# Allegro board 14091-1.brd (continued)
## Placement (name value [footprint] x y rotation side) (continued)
PR4535  140KR2F-1-GP  [R402H16]  154.08 23.62 0 bottom
PR4599  100KR2J-1-GP  [R402H16]  148.37 20.57 180 bottom
PR4601  2D2R3-1-U-GP  [R603H22]  32.42 207.65 90 bottom
PR4602  4K7R2F-GP  [R402H16]  20.86 209.17 180 bottom
PR4603  1KR2F-3-GP  [R402H16]  22.64 195.2 180 top
PR4605  1KR2F-3-GP  [R402H16]  23.15 204.49 270 top
PR4606  2K61R2F-1-GP  [R402H16]  20.61 195.2 0 top
PR4608  13K7R2F-GP  [R402H16]  19.72 198.63 270 bottom
PR4609  0R2J-2-GP  [R402H16]  25.69 190.5 0 top
PR4610  NTC-100K-12-GP-U  [NTC-402H22-U]  40.42 168.53 90 top
PR4612  20KR2F-L-GP  [R402H16]  19.34 203.58 270 bottom
PR4613  32K4R2F-1-GP  [R402H16]  23.15 202.61 270 top
PR4614  84K5R2F-GP  [R402H16]  23.15 200.7 90 top
PR4615  10KR2F-2-GP  [R402H16]  19.59 192.41 0 bottom
PR4616  100R2F-L1-GP-U  [R402H14]  23.66 192.41 180 top
PR4617  2K43R2F-GP  [R402H16]  23.02 208.03 0 top
PR4618  45D3R2F-L-GP  [R402H16]  24.67 190.5 0 top
PR4620  51KR2F-L-GP  [R402H16]  23.15 198.81 270 top
PR4621  140KR2F-1-GP  [R402H16]  25.69 194.31 180 bottom
PR4622  100KR2F-L1-GP  [R402H16]  19.34 206.76 90 bottom
PR4623  7K5R3F-2-GP  [R603H22]  26.96 192.79 0 top
PR4624  1KR2F-3-GP  [R402H16]  19.59 209.63 0 bottom
PR4625  13K7R2F-GP  [R402H16]  29.88 192.41 0 top
PR4626  30K9R2F-GP  [R402H16]  19.34 205.61 270 bottom
PR4627  7K5R3F-2-GP  [R603H22]  19.34 197.21 90 bottom
PR4628  49D9R2F-GP  [R402H16]  19.34 207.77 90 bottom
PR4629  59KR2F-GP  [R402H16]  28.61 195.2 180 bottom
PR4630  14K7R2F-L-GP  [R402H16]  23.3 208.15 270 bottom
PR4631  1K24R2F-GP  [R402H16]  29.47 191.97 90 bottom
PR4632  NTC-100K-12-GP-U  [NTC-402H22-U]  42.45 186.31 90 top
PR4633  220KR2F-GP  [R402H16]  22.84 211.46 0 bottom
PR4635  1K24R2F-GP  [R402H16]  30.36 196.06 0 top
PR4636  110KR3F-GP  [R603H22]  30.39 210.57 180 bottom
PR4637  523KR2F-GP  [R402H16]  23.86 211.46 180 bottom
PR4638  1KR2F-3-GP  [R402H16]  29.12 208.66 90 top
PR4639  2D2R3-1-U-GP  [R603H22]  32.29 209.55 0 top
PR4640  909R2F-GP  [R402H16]  32.55 195.2 180 bottom
PR4641  4K99R2F-L-GP  [R402H16]  32.39 196.06 180 top
PR4642  110KR3F-GP  [R603H22]  25.76 211.71 270 bottom
PR4644  NTC-100K-12-GP-U  [NTC-402H22-U]  34.2 186.31 90 top
PR4645  12K7R2F-GP  [R402H16]  32.42 192.91 90 bottom
PR4646  2D2R3-1-U-GP  [R603H22]  32.29 196.85 270 bottom
PR4647  909R2F-GP  [R402H16]  31.53 210.19 0 bottom
PR4648  12K7R2F-GP  [R402H16]  33.05 209.8 90 bottom
PR4649  NTC-100K-12-GP-U  [NTC-402H22-U]  52.74 217.3 270 top
PR4650  22K6R2F-1-GP  [R402H16]  29.62 203.45 270 top
PR4651  NTC-220K-GP-U  [NTC-402H22-U]  55.28 217.3 270 top
PR4652  1KR2F-3-GP  [R402H16]  26.45 207.77 270 bottom
PR4653  3K57R2F-GP  [R402H16]  29.12 210.19 0 bottom
PR4654  14KR2F-GP  [R402H16]  29.62 204.47 270 top
PR4655  12K4R2F-GP  [R402H16]  28.48 200.28 270 top
PR4656  10R2F-L-GP  [R402H14]  28.1 210.19 180 bottom
PR4657  10R2F-L-GP  [R402H14]  26.96 210.19 180 bottom
PR4658  3K57R2F-GP  [R402H16]  25.94 210.19 0 bottom
PR4660  0R0402-PAD-2-GP  [0R0402-PAD-1]  22.64 195.2 0 bottom
PR4661  2KR2F-3-GP  [R402H16]  33.41 196.06 0 top
PR4662  49D9R2F-GP  [R402H16]  21.62 195.2 0 bottom
PR4663  100R2F-L1-GP-U  [R402H14]  24.67 195.2 0 bottom
PR4664  1KR2F-3-GP  [R402H16]  24.67 192.41 180 top
PR4665  -  [0R0402-PAD]  19.59 195.2 180 bottom
PR4666  -  [0R0402-PAD]  20.61 195.2 180 bottom
PR4667  2D2R3F-L-GP  [R603H24]  32.77 200.18 270 bottom
PR4668  10R2F-L-GP  [R402H14]  23.66 195.2 0 bottom
PR4669  2KR2F-3-GP  [R402H16]  19.59 195.2 180 top
PR4701  -  [0R0805-PAD]  24.93 172.59 0 top
PR4702  -  [0R0805-PAD]  22.89 172.59 0 top
PR4703  -  [0R0805-PAD]  20.86 172.59 0 top
PR4704  -  [0R0805-PAD]  20.86 172.59 180 bottom
PR4705  -  [0R0805-PAD]  22.89 172.59 180 bottom
PR4706  -  [0R0805-PAD]  24.93 172.59 180 bottom
PR4707  2D2R5J-1-GP  [R805H24]  29.12 186.94 270 top
PR4801  -  [0R0805-PAD]  32.55 216.79 0 bottom
PR4802  -  [0R0805-PAD]  35.47 215.82 270 bottom
PR4803  -  [0R0805-PAD]  28.48 216.79 0 bottom
PR4805  -  [0R0805-PAD]  43.21 192.15 0 bottom
PR4806  -  [0R0805-PAD]  35.09 192.15 0 bottom
PR4807  -  [0R0805-PAD]  37.12 192.15 0 bottom
PR4808  -  [0R0805-PAD]  39.15 192.15 0 bottom
PR4809  -  [0R0805-PAD]  35.47 213.87 270 bottom
PR4810  -  [0R0805-PAD]  30.51 216.79 0 bottom
PR4811  -  [0R0805-PAD]  45.25 192.15 0 bottom
PR4812  -  [0R0805-PAD]  41.18 192.15 0 bottom
PR4813  2D2R5J-1-GP  [R805H24]  45.63 212.98 90 bottom
PR4814  2D2R5J-1-GP  [R805H24]  46.13 197.74 90 bottom
PR5001  -  [0R0805-PAD]  27.72 166.75 90 top
PR5002  -  [0R0805-PAD]  27.72 168.78 90 top
PR5004  -  [0R0805-PAD]  27.72 170.81 90 top
PR5005  2D2R2F-GP  [R402H16]  23.43 164.97 270 top
PR5101  620KR2F-GP  [R402H16]  79.92 215.14 270 bottom
PR5102  39K2R2F-L-GP  [R402H16]  80.17 208.91 0 bottom
PR5103  2D2R3-1-U-GP  [R603H22]  90.58 210.82 270 bottom
PR5105  5D1R2F-GP  [R402H16]  82.96 216.92 270 bottom
PR5106  10KR2F-2-GP  [R402H16]  81.44 216.41 180 bottom
PR5108  -  [0R0805-PAD]  90.33 208.28 270 top
PR5110  48D7KR2F-GP  [R402H16]  81.19 208.91 180 bottom
PR5111  7K5R2F-1DL-GP  [R402H16]  86.9 216.79 180 bottom
PR5112  -  [0R0805-PAD]  82.08 223.77 270 bottom
PR5114  2D2R5J-1-GP  [R805H24]  97.44 221.23 0 bottom
PR5116  -  [0R0805-PAD]  90.33 206.25 270 top
PR5118  -  [0R0603-PAD]  85.63 216.79 0 bottom
PR5121  -  [0R0805-PAD]  82.08 219.71 270 bottom
PR5122  -  [0R0805-PAD]  80.68 205.99 0 bottom
PR5125  -  [0R0805-PAD]  82.71 205.99 0 bottom
PR5127  -  [0R0805-PAD]  82.08 221.74 270 bottom
PR5202  470KR2F-GP  [R402H16]  22.26 151.89 90 top
PR5204  -  [0R0805-PAD]  30.26 141.48 180 top
PR5207  23K7R2F-GP  [R402H16]  22.26 152.91 90 top
PR5208  10KR2F-2-GP  [R402H16]  22.26 153.92 270 top
PR5210  2D2R3-1-U-GP  [R603H22]  24.77 149 180 top
PR5212  10KR2J-3-GP  [R402H16]  22.26 147.57 90 top
PR5214  2D2R5J-1-GP  [R805H24]  35.72 149.73 90 bottom
PR5215  -  [0R0805-PAD]  26.2 141.48 180 top
PR5217  0R2J-2-GP  [R402H16]  21.88 150.37 0 top
PR5218  10KR2J-3-GP  [R402H16]  22.26 148.84 270 top
PR5219  40K2R2F-GP  [R402H16]  22.74 145.11 270 bottom
PR5221  -  [0R0805-PAD]  28.23 141.48 180 top
PR5242  10KR2F-2-GP  [R402H16]  95.16 122.3 0 top
PR5245  -  [0R0402-PAD]  89.57 119.89 0 top
PR5246  10KR2J-3-GP  [R402H16]  84.41 124.21 180 top
PR5257  1KR2J-1-GP  [R402H16]  91.09 120.27 270 top
PR5258  -  [0R0805-PAD]  32.29 141.48 180 top
PR5297  100KR2J-1-GP  [R402H16]  35.47 48.77 90 bottom
PR5298  120KR2F-L-GP  [R402H16]  35.47 47.75 270 bottom
PR5301  10R3J-3-GP  [R603H22]  116.37 70.61 0 top
PR5302  10KR2F-2-GP  [R402H16]  118.52 70.36 0 top
PR5303  2D2R6J-3-GP  [R1206H28]  112.15 68.88 270 top
PR5304  10KR2F-2-GP  [R402H16]  120.94 78.99 0 top
PR5305  20KR2F-L-GP  [R402H16]  119.54 70.36 180 top
PR5306  0R0402-PAD-2-GP  [0R0402-PAD-1]  122.97 79.12 0 top
PR5307  -  [0R0805-PAD]  125.89 72.26 90 top
PR5308  -  [0R0805-PAD]  125.89 74.3 90 top
PR5309  -  [0R0805-PAD]  101.38 78.49 270 top
PR5310  -  [0R0805-PAD]  101.38 74.42 270 top
PR5311  -  [0R0805-PAD]  101.38 76.45 270 top
PR5312  0R2J-2-GP  [R402H16]  117.51 78.49 180 top
PR5313  0R2J-2-GP  [R402H16]  118.7 79.43 0 top
PR5431  10KR2J-3-GP  [R402H16]  141.64 8.13 270 bottom
PR5478  1KR2J-1-GP  [R402H16]  135.92 101.73 90 top
PR5479  1KR2J-1-GP  [R402H16]  135.92 96.65 90 top
PR5480  1KR2J-1-GP  [R402H16]  135.92 98.68 90 bottom
PR5481  1R2F-GP  [R402H16]  122.97 98.04 180 top
PR5482  1KR2J-1-GP  [R402H16]  135.92 95.63 90 bottom
PR5485  1KR2J-1-GP  [R402H16]  135.92 101.73 90 bottom
PR5486  1KR2J-1-GP  [R402H16]  135.92 99.69 90 bottom
PR5487  0R0603-PAD-2-GP-U  [0R0603-PAD-1-U]  120.68 96.9 180 top
PR5488  9K31R2F-GP  [R402H16]  124.37 94.36 180 top
PR5489  1R2F-GP  [R402H16]  118.14 100.97 270 top
PR5490  1KR2J-1-GP  [R402H16]  135.92 97.66 90 top
PR5491  11KR2F-L-GP  [R402H16]  119.67 100.33 180 top
PR5492  2D2R5J-1-GP  [R805H24]  126.91 84.58 90 top
PR5498  2D2R5J-1-GP  [R805H24]  137.96 16 0 bottom
PR8401  56KR2F-GP  [R402H16]  115.6 100.84 0 top
PR8402  2D2R2F-GP  [R402H16]  114.97 104.39 270 top
PR8403  33KR2F-GP  [R402H16]  114.59 100.84 180 top
PR8404  100KR2J-1-GP  [R402H16]  108.62 100.97 180 top
PR8405  18KR2F-GP  [R402H16]  112.56 100.84 0 top
PR8501  10KR2J-3-GP  [R402H16]  107.86 68.83 0 top
PR8502  10R2F-L-GP  [R402H14]  84.87 76.33 0 top
PR8503  10KR2F-2-GP  [R402H16]  88.04 76.33 180 top
PR8504  6K98R2F-GP  [R402H16]  86.9 76.33 0 top
PR8505  -  [0R0402-PAD]  103.79 68.83 0 top
PR8506  -  [0R0805-PAD]  90.84 206.25 90 bottom
PR8507  -  [0R0805-PAD]  90.84 208.28 90 bottom
PR8509  0R2J-2-GP  [R402H16]  25.18 146.3 90 top
PR8510  0R0402-PAD-2-GP  [0R0402-PAD-1]  22.26 146.56 270 top
PR8511  0R0402-PAD-2-GP  [0R0402-PAD-1]  22.26 145.54 270 top
PR8512  0R2J-2-GP  [R402H16]  13.5 186.06 180 top
PR8513  0R2J-2-GP  [R402H16]  107.6 100.97 0 top
PR8514  10KR2F-2-GP  [R402H16]  110.14 99.82 90 top
PR8515  0R2J-2-GP  [R402H16]  121.95 79.6 180 top
PR8516  10KR2F-2-GP  [R402H16]  121.95 69.9 270 top
PR8517  0R2J-2-GP  [R402H16]  133.38 105.03 270 bottom
PR8518  0R2J-2-GP  [R402H16]  106.84 68.83 0 top
PR8519  3K3R2J-3-GP  [R402H16]  82.58 59.05 180 top
PR8520  3K3R2J-3-GP  [R402H16]  83.6 59.05 180 top
PR8521  0R2J-2-GP  [R402H16]  103.03 66.93 0 bottom
PR8522  100KR2F-L1-GP  [R402H16]  24.67 69.09 180 bottom
PR8523  100KR2J-1-GP  [R402H16]  36.36 56.77 0 top
PR8524  1MR2J-1-GP  [R402H16]  35.85 54.1 270 top
PR8527  0R2J-2-GP  [R402H16]  164.5 175.64 180 top
PSWD1  JOWLE-CON2-5-GP  [A2541WV0-1EX2PA-6T]  123.6 112.01 90 top
PT1  E820U2D5VM-14-GP  [ECAP-100D6D3H355]  106.08 95.63 0 top
PT2  SE47U25VM-14-GP  [SE361416H237]  137.32 76.2 90 top
PT3  E820U2D5VM-14-GP  [ECAP-100D6D3H355]  113.95 95.63 0 top
PT4  E820U2D5VM-14-GP  [ECAP-100D6D3H355]  106.08 87.5 0 top
PT4501  SE220U6D3VM-3GP  [SE3116H241]  135.03 7.87 90 top
PT4502  SE220U6D3VM-3GP  [SE3116H241]  145.07 7.87 90 top
PT4503  SE47U25VM-13-GP  [SE361414H241]  141.77 24.64 270 top
PT4504  SE47U25VM-13-GP  [SE361414H241]  132.37 24.64 90 top
PT4701  E820U2D5VM-6-GP  [ECAP-100D6D3H375]  52.74 186.56 0 top
PT4703  E820U2D5VM-6-GP  [ECAP-100D6D3H375]  52.87 178.69 90 top
PT4704  SE47U25VM-13-GP  [SE361414H241]  23.15 179.07 180 top
PT4801  E820U2D5VM-6-GP  [ECAP-100D6D3H375]  59.85 190.25 90 top
PT4802  E560U6D3VM-3-GP  [ECAP-100D6D3H375]  67.34 197.1 0 top
PT4803  SE47U25VM-13-GP  [SE361414H241]  37.88 208.41 0 top
PT4804  SE47U25VM-13-GP  [SE361414H241]  37.88 198.5 180 top
PT5001  E820U2D5VM-6-GP  [ECAP-100D6D3H375]  49.94 165.99 0 top
PT5101  SE330U2VDM-L-GP  [CT7343H83]  100.24 202.56 0 top
PT5102  SE330U2VDM-L-GP  [CT7343H83]  95.03 202.56 0 top
PT5103  SE47U25VM-13-GP  [SE361414H241]  88.3 216.28 0 top
PT5201  SE47U25VM-13-GP  [SE361414H241]  33.31 147.96 180 top
PT5202  E820U2D5VM-6-GP  [ECAP-100D6D3H375]  54.64 146.43 0 top
PT5203  E820U2D5VM-6-GP  [ECAP-100D6D3H375]  55.66 154.31 0 top
PT8501  E820U2D5VM-6-GP  [ECAP-100D6D3H375]  81.44 70.87 90 top
PU1  SIRA14DP-T1-GE3-GP  [PPAK-5PH45]  129.57 80.26 270 top
PU2  SIRA14DP-T1-GE3-GP  [PPAK-5PH45]  129.57 80.26 90 bottom
PU3  SIRA04DP-T1-GE3-GP  [PPAK-5PH45]  127.54 88.9 90 top
PU4401  SIS412DN-T1-GE3-GP  [PPAK-8P-2H45]  43.21 54.99 0 bottom
PU4402  SIS412DN-T1-GE3-GP  [PPAK-8P-2H45]  38.77 56.52 180 bottom
PU4403  AO4407AL-GP  [SOIC8H69]  64.93 37.47 180 top
PU4404  BQ24727RGRR-1-GP  [QFN20G3D5-G2D15H40]  42.32 45.21 90 bottom
PU4405  AO4407AL-GP  [SOIC8H69]  40.8 71.37 180 top
PU4501  RT8243BZQW-GP  [QFN20-G1D75H32]  152.69 22.23 270 top
PU4502  AON7506-GP  [PPAK-8P-3232H36]  141.13 19.3 0 bottom
PU4503  AON7410-GP  [PPAK-8P-3232H36]  145.58 20.83 180 bottom
PU4504  AON7506-GP  [PPAK-8P-3232H36]  134.78 19.3 0 bottom
PU4505  AON7410-GP  [PPAK-8P-3232H36]  130.34 20.83 180 bottom
PU4601  NCP81206MNTXG-GP-U3  [LFQFN52J6-G4D8-1H40]  25.94 201.55 180 bottom
PU4701  AON6520-GP  [PPAK-8P-5262H40]  30.39 175.9 90 top
PU4702  AON6510-GP  [PPAK-8P-5262H40]  32.16 182.5 270 top
PU4703  AON6510-GP  [PPAK-8P-5262H40]  32.16 182.5 90 bottom
PU4704  AON6520-GP  [PPAK-8P-5262H40]  30.39 175.9 270 bottom
PU4801  AON6520-GP  [PPAK-8P-5262H40]  44.99 215.26 90 top
PU4802  AON6510-GP  [PPAK-8P-5262H40]  46.77 208.66 90 bottom
PU4803  AON6510-GP  [PPAK-8P-5262H40]  46.77 208.66 270 top
PU4804  AON6520-GP  [PPAK-8P-5262H40]  44.99 195.45 90 top
PU4805  AON6510-GP  [PPAK-8P-5262H40]  46.77 202.06 90 bottom
PU4807  AON6510-GP  [PPAK-8P-5262H40]  46.77 202.06 270 top
PU5001  AON7410-GP  [PPAK-8P-3232H36]  33.43 166.12 90 top
PU5002  AON7506-GP  [PPAK-8P-3232H36]  34.96 161.67 270 top
PU5003  NCP81253MNTBG-GP-U2  [LFDFN8G2-G1309H40]  26.7 162.18 90 top
PU5102  AON6510-GP  [PPAK-8P-5262H40]  101.76 220.6 0 bottom
PU5103  AON6520-GP  [PPAK-8P-5262H40]  93 222.5 180 bottom
PU5104  RT8207PGQW-GP  [QFN20-G1D75H32]  85.25 211.58 0 bottom
PU5201  RT8237CZQW-2-GP  [DFN10G3-G265175H32]  23.66 149.1 270 bottom
PU5202  AON6520-GP  [PPAK-8P-5262H40]  34.7 145.41 270 bottom
PU5203  AON6510-GP  [PPAK-8P-5262H40]  36.48 154.05 90 bottom
PU5301  RT6220AGQUF-GP  [QFN16J3H24]  119.54 74.93 270 top
PU5302  APL5930KAI-TRG-1-GP  [SOIC8-G3530H63]  89.7 124.33 90 top
PU5409  SIRA04DP-T1-GE3-GP  [PPAK-5PH45]  127.54 88.9 270 bottom
PU8401  RT8068AZQWID-GP-U  [DFN10G3-G265175H32]  111.41 104.39 90 top
PU8501  APL5912-KAC-TRG-GP  [SOIC8-G3530H63]  95.66 68.45 270 top
PWRCN1  ACES-CON10-30-GP  [51530-01041-W01]  26.75 22.5 270 top
Q1  2N7002A-7-GP  [SOT23DGS2D4H48]  41.94 116.2 270 top
Q2  MMBT3904-4-GP  [SOT23CBE2D4H44]  143.04 116.08 0 top
Q3  2N7002A-7-GP  [SOT23DGS2D4H48]  153.83 209.17 270 bottom
Q4  DMN5L06K-7-GP  [SOT23DGS2D4H48]  153.45 118.62 0 top
Q5  2N7002A-7-GP  [SOT23DGS2D4H48]  38.13 118.11 270 top
Q6  2N7002EDW-2-GP  [SOT-363H44]  150.53 77.98 0 top
Q8  2N7002H-GP  [SOT23DGS2D4H44]  126.53 44.58 180 top
Q10  MMBT3904-4-GP  [SOT23CBE2D4H44]  38.13 121.67 90 top
Q12  2N7002A-7-GP  [SOT23DGS2D4H48]  163.99 46.23 90 bottom
Q22  MMBT3904-4-GP  [SOT23CBE2D4H44]  42.71 28.32 270 bottom
Q24  AZ5125-02S-R7G-GP  [SOT23-2D4-312H46]  177.96 85.47 0 top
Q28  2N7002-11-GP  [SOT23DGS2D4H44]  168.56 87.25 270 top
Q31  MMBT3904-4-GP  [SOT23CBE2D4H44]  151.67 82.68 0 top
Q36  MMBT3904DW-GP  [SOT-363H44]  32.55 7.87 90 top
Q43  AO4468L-GP  [SOIC8H69]  124.62 7.75 90 bottom
Q44  AO3413L-GP  [SOT23DGS2D8H50]  41.94 6.86 180 bottom
Q45  MMBT3904-4-GP  [SOT23CBE2D4H44]  50.45 36.45 180 bottom
Q46  AZ5125-02S-R7G-GP  [SOT23-2D4-312H46]  84.11 41.66 270 top
Q47  2N7002A-7-GP  [SOT23DGS2D4H48]  55.02 36.32 0 bottom
Q48  MMBT3904-4-GP  [SOT23CBE2D4H44]  91.35 85.47 180 bottom
Q56  2N7002A-7-GP  [SOT23DGS2D4H48]  157.01 78.11 270 bottom
Q57  AZ5125-02S-R7G-GP  [SOT23-2D4-312H46]  174.02 85.47 0 top
Q65  2N7002KDW-1-GP  [SOT-363H44]  127.41 15.62 0 bottom
Q68  2N7002A-7-GP  [SOT23DGS2D4H48]  35.21 21.97 90 top
Q76  2N7002A-7-GP  [SOT23DGS2D4H48]  165.51 91.82 0 top
Q77  AO3413L-GP  [SOT23DGS2D8H50]  159.93 92.2 0 top
Q100  MMBT3904-4-GP  [SOT23CBE2D4H44]  42.96 6.99 0 top
Q101  MMBT3904-4-GP  [SOT23CBE2D4H44]  47.53 6.99 0 top
Q102  MMBT3904-4-GP  [SOT23CBE2D4H44]  46.52 6.99 0 bottom
Q123  2N7002KDW-1-GP  [SOT-363H44]  98.33 85.34 270 top
Q128  MMBT3904-4-GP  [SOT23CBE2D4H44]  150.02 209.17 90 bottom
Q1211  AO3413L-GP  [SOT23DGS2D8H50]  146.46 201.68 0 bottom
Q1212  2N7002A-7-GP  [SOT23DGS2D4H48]  25.18 12.83 180 bottom
Q1214  MMBT3904-4-GP  [SOT23CBE2D4H44]  25.94 27.18 0 bottom
Q1217  2N7002KDW-1-GP  [SOT-363H44]  122.08 16.26 90 bottom
Q1229  2N7002K-2-GP  [SOT23DGS2D4H44]  146.21 223.9 90 top
Q1249  2N7002A-7-GP  [SOT23DGS2D4H48]  143.8 30.23 270 top
Q1250  AO4286-GP  [SOIC8H69]  39.28 35.31 270 bottom
Q5008  2N7002A-7-GP  [SOT23DGS2D4H48]  151.93 55.24 90 top
Q6701  2N7002KDW-GP  [SOT-363H44]  102.78 64.9 270 top
Q6705  2N7002A-7-GP  [SOT23DGS2D4H48]  47.02 120.65 90 top
Q9501  2N7002KDW-GP  [SOT-363H44]  83.22 54.36 270 bottom
Q9502  2N7002KDW-GP  [SOT-363H44]  83.22 54.38 270 top
Q9503  2N7002KDW-GP  [SOT-363H44]  83.2 50.46 270 top
Q9601  AO3418L-GP  [SOT23DGS2D8H50]  62.01 66.17 180 bottom
Q9602  LMBT3906LT1G-1-GP  [SOT23CBE2D4H44]  68.49 66.42 270 bottom
Q9614  2N7002KDW-GP  [SOT-363H44]  50.58 56.01 270 top
Q9619  AO3418L-GP  [SOT23DGS2D8H50]  60.1 50.8 90 bottom
Q9620  2N7002KDW-GP  [SOT-363H44]  144.56 77.47 0 top
Q9622  MMBT3904DW-GP  [SOT-363H44]  155.86 41.91 90 bottom
Q9626  2N7002A-7-GP  [SOT23DGS2D4H48]  160.56 51.56 270 bottom
Q9627  2N7002KDW-GP  [SOT-363H44]  163.99 41.4 270 bottom
Q9628  DMN5L06K-7-GP  [SOT23DGS2D4H48]  157.01 118.62 0 top
Q9629  2N7002H-GP  [SOT23DGS2D4H44]  146.59 116.08 0 top
Q9631  MMBT3904DW-GP  [SOT-363H44]  24.8 21.84 0 bottom
Q9632  MMBT3904DW-GP  [SOT-363H44]  55.41 79.5 90 top
Q9633  MMBT3904DW-GP  [SOT-363H44]  55.41 79.25 270 bottom
Q9634  2N7002A-7-GP  [SOT23DGS2D4H48]  35.09 140.21 0 top
Q9635  MMBT3904DW-GP  [SOT-363H44]  22.64 143.38 90 top
Q9636  2N7002A-7-GP  [SOT23DGS2D4H48]  16.47 186.69 90 top
Q9637  MMBT3904DW-GP  [SOT-363H44]  16.67 183.39 270 top
Q9638  2N7002A-7-GP  [SOT23DGS2D4H48]  16.67 179.96 90 top
Q9639  MMBT3904DW-GP  [SOT-363H44]  16.67 176.53 270 top
Q9641  2N7002H-GP  [SOT23DGS2D4H44]  150.91 71.12 0 top
Q9642  MMBT3904-4-GP  [SOT23CBE2D4H44]  82.2 224.03 0 top
Q9643  2N7002A-7-GP  [SOT23DGS2D4H48]  164.12 65.53 270 top
Q9644  MMBT3906-4-GP  [SOT23CBE2D4H44]  112.81 121.79 180 bottom
Q9646  2N7002KDW-GP  [SOT-363H44]  24.67 14.48 90 top
Q9647  AO3413L-GP  [SOT23DGS2D8H50]  41.69 100.08 0 bottom
Q9648  2N7002A-7-GP  [SOT23DGS2D4H48]  96.81 66.93 270 bottom
Q9649  AO3413L-GP  [SOT23DGS2D8H50]  87.28 61.09 0 bottom
Q9650  MMBT3904DW-GP  [SOT-363H44]  15.53 159.13 0 top
Q9651  2N7002A-7-GP  [SOT23DGS2D4H48]  38.01 99.95 180 bottom
Q9652  2N7002A-7-GP  [SOT23DGS2D4H48]  160.43 170.43 180 top
Q9653  MMBT3904DW-GP  [SOT-363H44]  160.82 175.13 180 top
Q9654  MMBT3904DW-GP  [SOT-363H44]  77.88 224.41 270 top
R1  100KR2J-1-GP  [R402H16]  123.1 223.77 180 top
R2  0R6J-3-GP  [R1206H28]  42.83 114.81 270 bottom
R5  10R2F-L-GP  [R402H14]  42.2 25.65 270 top
R8  330R3J-L-GP  [R603H22]  44.48 117.22 180 top
R10  8K2R2J-3-GP  [R402H16]  146.85 207.14 90 bottom
R12  10KR2J-3-GP  [R402H16]  157.64 200.66 90 bottom
R13  39K2R2F-L-GP  [R402H16]  143.67 204.72 180 bottom
R14  0R2J-2-GP  [R402H16]  125.89 219.07 270 top
R15  -  [0R0402-PAD]  164.37 206.38 90 top
R19  1MR2J-1-GP  [R402H16]  39.02 115.7 270 top
R20  470KR2F-GP  [R402H16]  35.21 116.84 90 top
R22  0R0402-PAD-2-GP  [0R0402-PAD-1]  106.46 216.41 270 top
R23  0R0402-PAD-2-GP  [0R0402-PAD-1]  106.46 217.42 270 top
R24  0R3J-0-U-GP  [R603H22]  164.5 186.94 180 top
R26  100KR2J-1-GP  [R402H16]  35.21 117.86 90 top
R27  D33R6F-GP  [R1206H26]  45.37 37.97 270 bottom
R30  100KR2J-1-GP  [R402H16]  35.72 119.38 180 top
R33  100KR2J-1-GP  [R402H16]  41.05 122.17 270 top
R37  0R1206-PAD-1-GP  [0R1206-PAD-1]  33.56 21.08 180 bottom
R39  22R2J-2-GP  [R402H16]  43.09 121.16 90 top
R41  10KR2J-3-GP  [R402H16]  43.09 122.17 270 top
R42  10KR2J-3-GP  [R402H16]  41.05 121.16 270 top
R45  100R2F-L1-GP-U  [R402H14]  30.13 27.18 90 bottom
R51  -  [0R0402-PAD]  32.67 42.55 0 top
R53  -  [0R0402-PAD]  31.17 40.13 90 top
R56  -  [0R0402-PAD]  31.66 34.42 180 bottom
R59  -  [0R0402-PAD]  30.64 34.42 180 bottom
R61  1KR2F-3-GP  [R402H16]  38.31 20.45 180 bottom
R65  0R5J-5-GP  [R805H24]  41.05 31.37 270 bottom
R68  100R2F-L1-GP-U  [R402H14]  11.84 219.46 90 top
R71  2K2R2J-2-GP  [R402H16]  12.23 220.98 0 top
R73  20KR2J-L2-GP  [R402H16]  17.18 207.65 180 top
R74  0R0402-PAD-2-GP  [0R0402-PAD-1]  18.7 209.17 0 top
R76  8K2R2F-1-GP  [R402H16]  17.18 209.55 180 top
R80  4K7R2J-2-GP  [R402H16]  17.18 211.46 0 top
R82  10KR2F-2-GP  [R402H16]  30.64 28.83 0 bottom
R101  -  [0R0805-PAD]  8.42 210.82 0 bottom
R117  8K2R2J-3-GP  [R402H16]  147.02 111.84 270 top
R118  8K2R2J-3-GP  [R402H16]  151.16 117.47 180 top
R124  1KR2J-1-GP  [R402H16]  156.24 121.03 90 top
R131  0R2J-2-GP  [R402H16]  44.23 22.61 90 top
R132  100KR2J-1-GP  [R402H16]  42.32 21.59 270 top
R133  4K7R2J-2-GP  [R402H16]  43.67 24.13 180 top
R134  10KR2J-3-GP  [R402H16]  44.23 21.59 270 top
R135  4K7R2J-2-GP  [R402H16]  45.25 25.65 270 bottom
R138  10KR2J-3-GP  [R402H16]  42.71 23.11 0 bottom
R139  4K7R2J-2-GP  [R402H16]  43.72 24.13 180 bottom
R143  1KR2J-1-GP  [R402H16]  44.23 22.61 270 bottom
R144  100KR2J-1-GP  [R402H16]  45.25 24.64 270 bottom
R151  10KR2J-3-GP  [R402H16]  128.56 110.87 0 top
R153  1KR2J-1-GP  [R402H16]  108.24 122.3 270 bottom
R183  -  [0R0805-PAD]  17.69 191.39 180 top
R185  -  [0R0805-PAD]  15.65 191.39 180 top
R202  2K1R2F-GP  [R402H16]  48.04 114.05 0 top
R203  2K1R2F-GP  [R402H16]  49.06 114.05 180 top
R207  0R0402-PAD-2-GP  [0R0402-PAD-1]  155.86 81.66 0 top
R208  47KR2F-GP  [R402H16]  154.85 83.69 0 top
R209  33R2J-2-GP  [R402H16]  156.24 76.07 90 top
R210  47KR2F-GP  [R402H16]  156.88 81.66 180 top
R212  68R2F-GP  [R402H16]  156.75 69.93 270 top
R213  10KR2J-3-GP  [R402H16]  155.86 79.76 0 top
R215  0R0603-PAD-2-GP-U  [0R0603-PAD-1-U]  160.13 86.87 0 top
R216  0R3J-0-U-GP  [R603H22]  179.61 82.04 270 top
R220  10R2F-L-GP  [R402H14]  171.1 82.93 90 top
R221  10KR2J-3-GP  [R402H16]  173.64 82.42 0 top
R222  -  [0R0402-PAD]  159.16 70.05 180 top
R223  2K2R2J-2-GP  [R402H16]  171.1 84.96 90 top
R225  1KR2J-1-GP  [R402H16]  171.1 83.95 90 top
R230  2K1R2F-GP  [R402H16]  49.06 108.33 0 top
R249  10KR2J-3-GP  [R402H16]  125.26 57.66 270 top
R250  17K8R2F-GP  [R402H16]  143.92 41.27 0 top
R251  1KR2J-1-GP  [R402H16]  124.75 56.13 0 top
R252  10KR2F-2-GP  [R402H16]  144.56 44.7 90 top
R253  2K2R2J-2-GP  [R402H16]  132.37 49.53 270 bottom
R255  6K49R2F-1-GP  [R402H16]  142.65 43.69 270 top
R256  -  [0R0402-PAD]  123.73 56.13 0 top
R257  10KR2J-3-GP  [R402H16]  148.24 60.33 270 top
R259  10KR2F-2-GP  [R402H16]  142.65 45.64 270 top
R260  10KR2F-2-GP  [R402H16]  143.8 48.01 0 bottom
R261  2K2R2J-2-GP  [R402H16]  169.96 75.31 180 top
R262  2K2R2J-2-GP  [R402H16]  168.44 74.55 90 top
R264  10KR2J-3-GP  [R402H16]  123.6 61.47 0 top
R265  10KR2J-3-GP  [R402H16]  143.92 74.55 0 top
R266  10KR2F-2-GP  [R402H16]  169.96 71.5 180 top
R267  5K1R2F-2-GP  [R402H16]  170.98 71.5 180 top
R268  20KR2F-L-GP  [R402H16]  167.34 78.99 0 top
R272  2K2R2J-2-GP  [R402H16]  169.96 77.47 0 top
R277  10KR2J-3-GP  [R402H16]  127.11 47.5 180 top
R279  10KR2J-3-GP  [R402H16]  129.07 54.74 90 bottom
R280  10KR2F-2-GP  [R402H16]  129.07 53.72 270 bottom
R281  10KR2J-3-GP  [R402H16]  169.96 73.41 0 top
R282  10KR2J-3-GP  [R402H16]  133.26 64.52 180 bottom
R283  10KR2J-3-GP  [R402H16]  129.07 51.69 270 bottom
R284  10R2F-L-GP  [R402H14]  168.44 73.53 90 top
R286  1KR2J-1-GP  [R402H16]  139.23 45.34 0 top
R287  1KR2J-1-GP  [R402H16]  27.85 33.27 270 bottom
R288  100KR2J-1-GP  [R402H16]  147.48 74.93 0 top
R290  10KR2F-2-GP  [R402H16]  152.05 73.53 90 top
R291  -  [0R0402-PAD]  136.18 50.16 180 bottom
R293  20KR2J-L2-GP  [R402H16]  148.5 74.04 0 top
R294  33R2J-2-GP  [R402H16]  140.11 62.1 270 bottom
R295  0R0402-PAD-2-GP  [0R0402-PAD-1]  132.88 45.34 0 top
R296  10KR2J-3-GP  [R402H16]  139.99 70.1 90 top
R297  0R0402-PAD-2-GP  [0R0402-PAD-1]  131.86 45.34 0 top
R298  33R2J-2-GP  [R402H16]  138.46 70.61 0 top
R299  243R2F-2-GP  [R402H16]  48.29 98.68 90 top
R300  0R0603-PAD-2-GP-U  [0R0603-PAD-1-U]  160.69 65.53 90 top
R301  0R0603-PAD-2-GP-U  [0R0603-PAD-1-U]  158.78 81.15 90 top
R302  5K11R2F-L1-GP  [R402H16]  79.03 85.72 180 bottom
R303  1KR2J-1-GP  [R402H16]  121.24 48.26 0 top
R304  0R3J-0-U-GP  [R603H22]  132.24 55.75 0 bottom
R305  -  [0R0603-PAD]  133.51 55.75 180 bottom
R306  0R2J-2-GP  [R402H16]  122.21 50.8 90 top
R307  0R2J-2-GP  [R402H16]  122.21 51.82 90 top
R308  10KR2F-2-GP  [R402H16]  134.4 61.72 90 bottom
R309  10KR2F-2-GP  [R402H16]  134.4 60.58 90 bottom
R310  10KR2F-2-GP  [R402H16]  134.27 59.41 90 bottom
R311  10KR2F-2-GP  [R402H16]  141.13 61.09 270 bottom
R312  10KR2F-2-GP  [R402H16]  140.11 63.12 270 bottom
R313  10KR2F-2-GP  [R402H16]  136.69 61.72 0 bottom
R314  1KR2J-1-GP  [R402H16]  152.56 76.83 180 top
R316  10KR2J-3-GP  [R402H16]  147.48 68.07 180 top
R317  10KR2J-3-GP  [R402H16]  142.53 70.61 180 top
R318  4K7R2J-2-GP  [R402H16]  128.81 45.34 180 top
R319  100KR2F-L1-GP  [R402H16]  148.88 82.68 90 top
R320  243R2F-2-GP  [R402H16]  47.79 95.63 90 top
R321  10KR2F-2-GP  [R402H16]  124.72 53.21 270 top
R322  1MR3F-GP  [R603H22]  148.5 81.53 270 top
R323  330R3J-L-GP  [R603H22]  131.02 42.42 270 top
R324  10KR2J-3-GP  [R402H16]  122.97 58.93 0 top
R327  2KR2J-1-GP  [R402H16]  121.95 58.93 180 top
R329  47KR2F-GP  [R402H16]  91.98 83.06 270 top
R332  0R0402-PAD-2-GP  [0R0402-PAD-1]  119.16 48.01 180 top
R333  0R2J-2-GP  [R402H16]  120.2 48.08 180 top
R334  0R0402-PAD-2-GP  [0R0402-PAD-1]  125.18 47.5 0 top
R335  1KR2J-1-GP  [R402H16]  139.99 71.12 270 top
R336  0R0402-PAD-2-GP  [0R0402-PAD-1]  137.45 70.61 0 top
R337  1KR2J-1-GP  [R402H16]  147.48 78.23 180 top
R338  1KR2J-1-GP  [R402H16]  133.56 67.97 270 top
R339  20KR2J-L2-GP  [R402H16]  135.03 68.58 180 top
R340  1KR2J-1-GP  [R402H16]  145.45 75.06 90 top
R341  -  [0R0402-PAD]  39.12 129.29 270 top
R342  0R2J-2-GP  [R402H16]  39.12 127.25 90 top
R343  1KR2J-1-GP  [R402H16]  61.27 129.16 270 top
R348  -  [0R0402-PAD]  61.37 133.73 270 top
R351  -  [0R0402-PAD]  63.79 129.16 90 top
R352  -  [0R0402-PAD]  61.45 132.72 270 top
R354  0R2J-2-GP  [R402H16]  94.14 85.09 90 bottom
R377  1KR2J-1-GP  [R402H16]  31.78 5.21 180 top
R378  8K2R2J-3-GP  [R402H16]  33.31 5.59 270 top
R379  -  [0R0402-PAD]  152.05 59.56 270 top
R380  10R3J-3-GP  [R603H22]  152.31 50.16 90 top
R381  0R0402-PAD-2-GP  [0R0402-PAD-1]  163.74 48.64 90 bottom
R382  0R0603-PAD-2-GP-U  [0R0603-PAD-1-U]  164.5 57.35 90 top
R383  0R0603-PAD-2-GP-U  [0R0603-PAD-1-U]  163.36 58.55 90 top
R384  0R0603-PAD-2-GP-U  [0R0603-PAD-1-U]  155.35 58.55 270 top
R385  10K5R3F-GP  [R603H22]  155.35 59.82 90 top
R386  10K5R3F-GP  [R603H22]  163.36 59.77 270 top
R387  0R0603-PAD-2-GP-U  [0R0603-PAD-1-U]  158.76 57.25 270 top
R388  100KR2J-1-GP  [R402H16]  158.15 51.18 180 bottom
R389  10KR5F-2-GP  [R805H24]  30.39 19.84 90 bottom
R390  20KR2J-L2-GP  [R402H16]  161.07 43.43 270 bottom
R391  4K7R2J-2-GP  [R402H16]  161.07 41.4 270 bottom
R392  10KR2J-3-GP  [R402H16]  155.1 43.94 270 bottom
R393  1KR2J-1-GP  [R402H16]  153.07 40.77 270 bottom
R394  10KR2J-3-GP  [R402H16]  159.57 40.89 0 bottom
R396  100KR2J-1-GP  [R402H16]  161.07 54.61 270 top
R397  10KR2F-2-GP  [R402H16]  139.73 48.06 180 bottom
R398  10KR2F-2-GP  [R402H16]  162.57 54.23 0 top
R399  0R0402-PAD-2-GP  [0R0402-PAD-1]  138.72 48.06 0 bottom
R400  0R0402-PAD-2-GP  [0R0402-PAD-1]  141.77 48.06 0 bottom
R401  1KR2J-1-GP  [R402H16]  67.39 187.58 180 top
R403  499R2F-2-GP  [R402H16]  68.41 187.58 0 top
R404  10KR2F-2-GP  [R402H16]  140.75 48.06 180 bottom
R406  1KR2J-1-GP  [R402H16]  34.98 7.72 270 bottom
R407  1MR3F-GP  [R603H22]  36.74 9.14 270 top
R412  2K49R2F-GP  [R402H16]  41.44 9.4 270 top
R413  0R2J-2-GP  [R402H16]  37.93 19.46 270 top
R419  1KR2J-1-GP  [R402H16]  65.69 181.61 0 top
R420  -  [0R0402-PAD]  67.98 181.1 90 top
R428  47R2J-2-GP  [R402H16]  84.49 35.43 180 top
R429  47R2J-2-GP  [R402H16]  83.35 35.43 180 top
R458  0R0402-PAD-2-GP  [0R0402-PAD-1]  179.74 150.62 0 bottom
R504  0R2J-2-GP  [R402H16]  80.81 206.25 90 top
R507  200KR2J-L1-GP  [R402H16]  80.81 208.53 90 top
R517  10KR2J-3-GP  [R402H16]  57.69 79.25 0 top
R523  10KR2J-3-GP  [R402H16]  52.61 80.9 90 bottom
R524  10KR2J-3-GP  [R402H16]  58.2 79.88 90 bottom
R530  10KR2J-3-GP  [R402H16]  56.42 50.67 270 top
R531  10KR2J-3-GP  [R402H16]  52.15 80.26 180 top
R533  10KR2J-3-GP  [R402H16]  51.47 82.17 0 top
R535  4K7R2J-2-GP  [R402H16]  52.61 77.72 90 top
R542  1KR2J-1-GP  [R402H16]  82.46 196.85 0 bottom
R601  49D9R2F-GP  [R402H16]  75.93 178.89 270 bottom
R602  -  [0R0402-PAD]  100.87 192.02 0 top
R603  100KR2J-1-GP  [R402H16]  64.68 187.32 180 top
R604  1KR2J-1-GP  [R402H16]  72.8 189.1 180 top
R605  1KR2J-1-GP  [R402H16]  73.82 189.1 180 top
R606  -  [0R0402-PAD]  100.62 132.08 180 top
R617  33KR2J-3-GP  [R402H16]  156.5 81.41 270 bottom
R618  0R2J-2-GP  [R402H16]  156.24 78.11 270 top
R627  1KR2J-1-GP  [R402H16]  168.44 72.52 90 top
R651  0R0402-PAD-2-GP  [0R0402-PAD-1]  138.72 44.83 270 bottom
R658  10KR2F-2-GP  [R402H16]  138.72 45.85 90 bottom
R702  0R2J-2-GP  [R402H16]  79.54 179.71 270 bottom
R703  -  [0R0402-PAD]  73.31 156.97 270 bottom
R705  0R0603-PAD-2-GP-U  [0R0603-PAD-1-U]  94.65 168.28 0 bottom
R707  -  [0R0402-PAD]  51.85 137.92 180 top
R708  -  [0R0402-PAD]  50.83 137.92 180 top
R709  -  [0R0402-PAD]  71.79 157.35 0 bottom
R718  15KR2F-GP  [R402H16]  125.13 12.45 270 bottom
R722  1MR2J-1-GP  [R402H16]  127.54 12.32 90 top
R723  -  [0R0402-PAD]  25.43 10.41 90 bottom
R724  75R3F-GP  [R603H22]  27.77 16.76 180 bottom
R729  0R2J-2-GP  [R402H16]  27.97 12.45 270 bottom
R730  75R3F-GP  [R603H22]  28.3 14.81 90 bottom
R731  4K7R2J-2-GP  [R402H16]  37.63 21.46 0 top
R732  100KR2J-1-GP  [R402H16]  127.54 15.75 90 top
R733  100KR2J-1-GP  [R402H16]  127.54 14.73 270 top
R735  75R3F-GP  [R603H22]  29.04 16.76 180 bottom
R741  0R5J-5-GP  [R805H24]  40.93 9.91 270 bottom
R742  1KR2F-3-GP  [R402H16]  33.87 26.64 180 top
R743  33R2J-2-GP  [R402H16]  32.34 26.14 270 top
R744  -  [0R0402-PAD]  32.34 27.15 270 top
R755  4K7R2J-2-GP  [R402H16]  32.04 25.15 270 bottom
R758  33R2J-2-GP  [R402H16]  30.13 26.16 90 bottom
R764  10KR2J-3-GP  [R402H16]  49.82 5.97 0 bottom
R774  10KR2J-3-GP  [R402H16]  44.23 7.95 180 bottom
R775  8K2R2J-3-GP  [R402H16]  47.02 9.4 90 top
R776  39K2R2F-L-GP  [R402H16]  45.25 7.87 0 top
R801  24D9R2F-L-GP  [R402H16]  85.38 169.29 90 bottom
R802  10KR2J-3-GP  [R402H16]  75.22 138.43 180 bottom
R803  10KR2J-3-GP  [R402H16]  76.49 138.43 180 bottom
R870  243R2F-2-GP  [R402H16]  48.67 111.25 270 bottom
R885  2K1R2F-GP  [R402H16]  49.06 108.33 180 bottom
R886  2K1R2F-GP  [R402H16]  47.02 108.33 0 bottom
R899  243R2F-2-GP  [R402H16]  48.7 106.78 270 bottom
R924  2K1R2F-GP  [R402H16]  63.41 104.52 0 bottom
R928  2K1R2F-GP  [R402H16]  62.39 104.52 180 bottom
R935  4K53R2F-1-GP  [R402H16]  99.98 99.31 270 top
R940  2KR2F-3-GP  [R402H16]  98.46 98.81 0 top
R943  8K45R2F-2-GP  [R402H16]  99.22 94.87 0 top
R945  2K1R2F-GP  [R402H16]  48.93 96.27 0 bottom
R946  2K1R2F-GP  [R402H16]  47.4 96.77 270 bottom
R948  2KR2F-3-GP  [R402H16]  98.2 94.87 0 top
R963  10KR2J-L-GP  [R402H15]  82.08 83.06 90 top
R1101  0R0603-PAD-2-GP-U  [0R0603-PAD-1-U]  81.62 153.85 0 bottom
R1102  0R0603-PAD-2-GP-U  [0R0603-PAD-1-U]  79.46 153.82 0 bottom
R1106  0R0603-PAD-2-GP-U  [0R0603-PAD-1-U]  82.79 153.85 0 bottom
R1108  -  [0R0402-PAD]  78.77 135.13 90 top
R1109  -  [0R0402-PAD]  96.27 128.73 0 top
R1111  0R2J-2-GP  [R402H16]  95.26 128.3 180 top
R1112  -  [0R0402-PAD]  52.87 141.73 0 top
R1114  -  [0R0402-PAD]  42.07 141.48 0 top
R1115  -  [0R0402-PAD]  97.29 128.73 0 top
R1116  -  [0R0402-PAD]  91.6 128.27 180 top
R1118  0R3J-0-U-GP  [R603H22]  85.76 130.15 90 top
R1120  -  [0R0402-PAD]  77.5 138.43 0 bottom
R1121  -  [0R0402-PAD]  59.6 147.19 90 top
R1122  -  [0R0402-PAD]  59.6 142.11 90 top
R1123  -  [0R0402-PAD]  78.77 134.11 90 top
R1124  -  [0R0402-PAD]  78.52 136.65 180 top
R1125  -  [0R0402-PAD]  44.23 141.48 0 top
R1126  -  [0R0402-PAD]  93.23 128.3 180 top
R1127  -  [0R0402-PAD]  70.65 140.41 90 top
R1128  0R2J-2-GP  [R402H16]  94.24 128.3 180 top
R1129  0R2J-2-GP  [R402H16]  81.44 135.13 270 top
R1130  -  [0R0402-PAD]  59.6 146.18 90 top
R1131  -  [0R0402-PAD]  59.6 143.13 90 top
R1132  -  [0R0402-PAD]  46.26 141.48 0 top
R1133  -  [0R0402-PAD]  59.6 144.15 90 top
R1134  -  [0R0402-PAD]  59.6 145.16 90 top
R1135  0R0603-PAD-2-GP-U  [0R0603-PAD-1-U]  85.76 131.32 90 top
R1136  -  [0R0402-PAD]  76.87 135.13 90 top
R1137  -  [0R0402-PAD]  80.55 140.21 0 bottom
R1138  -  [0R0402-PAD]  82.84 136.65 180 top
R1154  0R2J-2-GP  [R402H16]  115.98 201.04 90 top
R1155  0R2J-2-GP  [R402H16]  106.03 219.89 180 top
R1158  1KR2F-3-GP  [R402H16]  80.68 95.12 90 bottom
R1159  10KR2J-L-GP  [R402H15]  99.35 106.68 0 top
R1160  -  [0R0402-PAD]  98.23 106.66 0 top
R1161  1K69R2F-2-GP  [R402H16]  98.97 100.33 90 top
R1162  1KR2F-3-GP  [R402H16]  98.97 101.35 90 top
R1165  0R0402-PAD-2-GP  [0R0402-PAD-1]  97.47 89.26 270 top
R1166  0R0402-PAD-2-GP  [0R0402-PAD-1]  97.47 88.24 270 top
R1167  10KR2J-3-GP  [R402H16]  83.6 88.39 270 bottom
R1168  33R2J-2-GP  [R402H16]  83.6 89.48 270 bottom
R1169  33R2J-2-GP  [R402H16]  83.6 90.55 270 bottom
R1170  33R2J-2-GP  [R402H16]  88.04 86.74 90 bottom
R1171  33R2J-2-GP  [R402H16]  88.04 85.72 90 bottom
R1178  10KR2J-3-GP  [R402H16]  125.26 14.45 0 bottom
R1179  1KR2J-1-GP  [R402H16]  85.89 196.85 0 bottom
R1180  0R2J-2-GP  [R402H16]  48.8 5.97 180 bottom
R1183  10KR2J-3-GP  [R402H16]  40.67 5.97 0 top
R1193  0R0603-PAD-2-GP-U  [0R0603-PAD-1-U]  166.1 86.87 0 top
R1194  10KR2J-3-GP  [R402H16]  40.67 7.87 0 top
R1195  39K2R2F-L-GP  [R402H16]  162.72 92.84 270 top
R1200  40D2R2F-GP  [R402H16]  77.1 115.49 0 top
R1201  -  [0R0402-PAD]  130.97 130.18 90 bottom
R1202  -  [0R0402-PAD]  128.81 125.6 0 bottom
R1204  2K2R2J-2-GP  [R402H16]  83.85 76.33 180 top
R1205  4K99R2F-L-GP  [R402H16]  84.62 79.5 0 top
R1206  51D1R2F-GP  [R402H16]  87.92 84.96 270 top
R1207  51D1R2F-GP  [R402H16]  77 83.95 270 top
R1209  -  [0R0402-PAD]  113.95 201.04 90 top
R1210  249R2F-GP  [R402H16]  93.71 97.97 0 bottom
R1211  499R2F-2-GP  [R402H16]  94.72 97.97 180 bottom
R1212  1K8R2F-GP  [R402H16]  137.45 193.17 180 bottom
R1213  1K8R2F-GP  [R402H16]  132.37 193.04 0 bottom
R1214  24D9R2F-L-GP  [R402H16]  130.46 194.94 180 bottom
R1215  2R2F-GP  [R402H16]  129.45 193.04 180 bottom
R1217  -  [0R0402-PAD]  142.91 148.46 0 bottom
R1218  1K8R2F-GP  [R402H16]  139.61 152.53 90 bottom
R1219  1K8R2F-GP  [R402H16]  140.88 148.46 180 bottom
R1220  2R2F-GP  [R402H16]  144.05 149.35 0 bottom
R1221  24D9R2F-L-GP  [R402H16]  146.46 150.75 270 bottom
R1301  -  [0R0402-PAD]  146.59 129.29 90 bottom
R1302  10KR2J-3-GP  [R402H16]  146.08 127.76 180 bottom
R1304  1K8R2F-GP  [R402H16]  142.78 193.17 180 bottom
R1305  2R2F-GP  [R402H16]  143.8 193.17 180 bottom
R1306  24D9R2F-L-GP  [R402H16]  144.94 195.07 180 bottom
R1307  1K8R2F-GP  [R402H16]  144.94 193.17 0 bottom
R1501  100R2F-L1-GP-U  [R402H14]  71.79 151.64 90 bottom
R1502  200R2F-L-GP  [R402H16]  86.88 137.24 180 top
R1592  36R3F-GP  [R603H22]  144 33.45 90 bottom
R1593  4K7R2F-GP  [R402H16]  130.92 42.49 180 bottom
R1594  4K7R2F-GP  [R402H16]  129.9 42.49 180 bottom
R1596  4K7R2F-GP  [R402H16]  131.99 30.86 90 bottom
R1598  4K7R2F-GP  [R402H16]  132.95 42.49 180 bottom
R1603  113R2F-GP  [R402H16]  83.98 144.65 180 bottom
R1604  100R2F-L1-GP-U  [R402H14]  76.87 146.56 180 bottom
R1610  10KR2J-3-GP  [R402H16]  72.55 137.67 90 top
R1611  10KR2J-3-GP  [R402H16]  72.17 140.97 0 top
R1615  10KR2J-3-GP  [R402H16]  71.79 138.68 90 top
R1617  10KR2J-3-GP  [R402H16]  73.19 140.97 0 top
R1620  0R2J-2-GP  [R402H16]  125.89 217.81 270 top
R1621  0R2J-2-GP  [R402H16]  123.99 217.3 270 top
R1622  0R2J-2-GP  [R402H16]  123.99 218.44 270 top
R1659  10KR2J-3-GP  [R402H16]  148.5 66.17 0 top
R1660  10KR2J-3-GP  [R402H16]  147.48 66.17 180 top
R1661  10KR2J-3-GP  [R402H16]  148.12 63.63 270 top
R1662  10KR2J-3-GP  [R402H16]  151.57 66.22 180 top
R1663  10KR2J-3-GP  [R402H16]  148.12 64.64 90 top
R1684  10KR2J-3-GP  [R402H16]  65.57 133.1 180 top
R1685  10KR2J-3-GP  [R402H16]  64.55 133.1 0 top
R1687  10KR2J-3-GP  [R402H16]  70.26 133.48 180 top
R1688  10KR2J-3-GP  [R402H16]  68.61 133.48 0 top
R1689  -  [0R0402-PAD]  83.4 124.21 180 top
R1699  4K7R2J-2-GP  [R402H16]  105.57 59.82 0 top
R1700  10KR2J-3-GP  [R402H16]  108.87 59.82 0 top
R1707  10KR2J-3-GP  [R402H16]  122.08 223.77 180 top
R1708  0R5J-5-GP  [R805H24]  149.26 201.55 180 bottom
R1709  -  [0R0402-PAD]  106.46 218.44 90 top
R1710  0R2J-2-GP  [R402H16]  124.01 216.15 270 top
R1711  0R0402-PAD-2-GP  [0R0402-PAD-1]  106.46 214.38 270 top
R1712  0R0402-PAD-2-GP  [0R0402-PAD-1]  106.46 215.39 270 top
R1713  0R0402-PAD-2-GP  [0R0402-PAD-1]  106.46 212.34 270 top
R1714  0R0402-PAD-2-GP  [0R0402-PAD-1]  106.46 213.36 270 top
R1716  10KR2J-3-GP  [R402H16]  153.32 205.87 270 bottom
R1717  0R2J-2-GP  [R402H16]  123.99 219.71 270 top
R1718  0R0402-PAD-2-GP  [0R0402-PAD-1]  123.99 220.98 270 top
R1719  0R0402-PAD-2-GP  [0R0402-PAD-1]  123.99 222 90 top
R1727  15KR2F-GP  [R402H16]  163.48 118.36 0 top
R1728  10KR2J-3-GP  [R402H16]  162.97 119.86 270 top
R1729  1KR2J-1-GP  [R402H16]  161.32 123.57 180 top
R1730  1KR2J-1-GP  [R402H16]  27.85 35.31 270 bottom
R1731  10KR2J-3-GP  [R402H16]  27.85 32.26 270 bottom
R1732  1KR2J-1-GP  [R402H16]  27.85 30.23 270 bottom
R1733  10KR2J-3-GP  [R402H16]  27.85 31.24 270 bottom
R1734  10KR2J-3-GP  [R402H16]  27.85 34.29 270 bottom
R1751  75R3F-GP  [R603H22]  25.43 16.76 90 bottom
R1752  4K7R2J-2-GP  [R402H16]  27.97 11.43 90 bottom
R1753  10KR2J-3-GP  [R402H16]  24.32 30.07 90 bottom
R1754  10KR2J-3-GP  [R402H16]  23.63 25.27 180 bottom
R1755  33R2J-2-GP  [R402H16]  29.62 28.7 270 top
R1756  33R2J-2-GP  [R402H16]  29.32 24.18 270 bottom
R1757  10KR2J-3-GP  [R402H16]  24.32 31.09 270 bottom
R1758  4K7R2J-2-GP  [R402H16]  29.17 30.23 180 top
R1759  10KR2J-3-GP  [R402H16]  25.05 18.41 90 bottom
R1760  10KR2F-2-GP  [R402H16]  27.85 24 180 bottom
R1761  0R2J-2-GP  [R402H16]  32.8 21.46 0 top
R1767  1K5R3-GP  [R603H22]  141.13 40.89 0 top
R1777  470KR2F-GP  [R402H16]  119.74 12.65 180 bottom
R1778  470KR2F-GP  [R402H16]  127.54 13.46 270 top
R1779  1MR2J-1-GP  [R402H16]  121.83 13.72 180 bottom
R1780  100KR2J-1-GP  [R402H16]  119.77 14.53 0 bottom
R1781  100KR2J-1-GP  [R402H16]  119.79 17.27 0 bottom
R1782  4K7R2J-2-GP  [R402H16]  119.59 7.87 0 bottom
R1783  10KR2J-3-GP  [R402H16]  122.84 13.72 180 bottom
R1784  0R3J-0-U-GP  [R603H22]  160.18 188.09 90 top
R1785  10KR2J-3-GP  [R402H16]  27.97 10.41 90 bottom
R1801  -  [0R0402-PAD]  102.52 141.99 180 top
R1806  15R2J-GP  [R402H16]  86.16 134.42 90 top
R1807  15R2J-GP  [R402H16]  85.63 128.91 90 top
R1808  15R2J-GP  [R402H16]  83.73 133.35 180 top
R1809  15R2J-GP  [R402H16]  82.08 128.91 90 top
R1810  0R2J-2-GP  [R402H16]  81.06 212.34 0 bottom
R1811  15R2J-GP  [R402H16]  84.28 135.84 90 top
R1812  -  [0R0402-PAD]  86.16 135.43 270 top
R1816  2KR2F-3-GP  [R402H16]  32.16 8.51 270 bottom
R1817  15KR2F-GP  [R402H16]  30.77 5.21 0 top
R1819  10KR2J-3-GP  [R402H16]  41.44 10.41 90 top
R1822  1KR2J-1-GP  [R402H16]  82.08 140.59 270 bottom
R1823  1KR2J-1-GP  [R402H16]  81.95 138.68 90 bottom
R1824  1KR2J-1-GP  [R402H16]  85.76 132.97 180 top
R1825  1KR2J-1-GP  [R402H16]  86.77 132.91 0 top
R1826  1KR2J-1-GP  [R402H16]  84.74 132.84 180 top
R1827  1KR2J-1-GP  [R402H16]  82.08 129.92 90 top
R1832  1KR2J-1-GP  [R402H16]  79.54 140.21 180 bottom
R1833  10KR2J-3-GP  [R402H16]  92.36 128.27 180 bottom
R1834  1KR2J-1-GP  [R402H16]  85.86 137.24 0 top
R1836  1KR2J-1-GP  [R402H16]  108.24 121.28 90 bottom
R1837  1KR2J-1-GP  [R402H16]  100.62 126.24 0 top
R1838  1KR2J-1-GP  [R402H16]  159.29 119 180 top
R1846  1K5R3-GP  [R603H22]  59.55 39.42 90 bottom
R1847  240KR3-GP  [R603H22]  69.12 30.48 90 top
R1848  10KR3J-L1-GP  [R603H22]  69.76 34.29 90 top
R1849  10KR2J-3-GP  [R402H16]  51.47 38.86 270 bottom
R1850  47KR3J-L-GP  [R603H22]  69.76 26.92 0 top
R1851  33R2J-2-GP  [R402H16]  56.68 39.88 270 bottom
R1852  100KR2J-1-GP  [R402H16]  52.74 35.31 0 bottom
R1853  15KR2F-GP  [R402H16]  50.96 34.04 90 bottom
R1878  -  [0R0402-PAD]  125.94 11.3 90 bottom
R1879  1MR3F-GP  [R603H22]  98.48 109.71 180 top
R1880  10KR2J-3-GP  [R402H16]  97.7 103.12 90 top
R1881  10KR2J-3-GP  [R402H16]  97.7 104.14 90 top
R1882  10KR2J-3-GP  [R402H16]  89.44 85.47 0 top
R1883  4K7R2J-2-GP  [R402H16]  97.7 105.16 270 top
R1884  33R2J-2-GP  [R402H16]  94.52 84.58 180 top
R1885  10KR2J-3-GP  [R402H16]  95.54 85.47 0 top
R1886  10KR2J-3-GP  [R402H16]  90.46 83.57 180 top
R1887  10KR2J-3-GP  [R402H16]  93.51 85.47 180 top
R1888  100R2F-L1-GP-U  [R402H14]  79.03 112.27 270 bottom
R1889  100R2F-L1-GP-U  [R402H14]  74.71 113.28 90 bottom
R1890  40D2R2F-GP  [R402H16]  78.16 115.49 0 top
R1891  47R2J-2-GP  [R402H16]  83.98 77.98 90 top
R1892  10KR2J-L-GP  [R402H15]  82.08 84.07 90 top
R1893  10KR2J-L-GP  [R402H15]  78.65 84.2 270 bottom
R1894  100KR2J-1-GP  [R402H16]  89.06 82.17 0 top
R1895  10KR2J-L-GP  [R402H15]  82.08 81.03 90 top
R1896  47KR2F-GP  [R402H16]  92.49 85.47 180 top
R1897  1KR2F-3-GP  [R402H16]  79.41 87.25 270 bottom
R1899  4K75R2F-1-GP  [R402H16]  98.2 92.96 0 top
R1900  8K45R2F-2-GP  [R402H16]  99.22 92.96 0 top
R1901  200R2F-L-GP  [R402H16]  82.58 144.65 180 bottom
R1905  2K1R2F-GP  [R402H16]  47.02 108.33 180 top
R1906  40D2R2F-GP  [R402H16]  48.67 111.25 270 top
R1907  33R2J-2-GP  [R402H16]  102.52 161.93 270 top
R1908  33R2J-2-GP  [R402H16]  102.52 160.91 270 top
R1909  40D2R2F-GP  [R402H16]  48.9 92.08 270 top
R1910  150KR2J-GP  [R402H16]  102.52 163.96 270 top
R1911  33R2J-2-GP  [R402H16]  102.52 159.89 270 top
R1912  33R2J-2-GP  [R402H16]  102.52 162.94 270 top
R1920  0R2J-2-GP  [R402H16]  87.54 81.28 0 bottom
R1921  2K1R2F-GP  [R402H16]  48.29 91.19 0 bottom
R1922  2K1R2F-GP  [R402H16]  49.31 91.19 180 bottom
R1923  2K1R2F-GP  [R402H16]  48.44 93.82 270 bottom
R1924  2K1R2F-GP  [R402H16]  48.31 92.81 90 bottom
R1925  0R2J-2-GP  [R402H16]  125.89 220.34 270 top
R1931  0R2J-2-GP  [R402H16]  106.03 221.77 180 top
R1932  10KR2J-3-GP  [R402H16]  143.54 224.54 180 top
R1946  4K7R2J-2-GP  [R402H16]  143.54 70.61 0 top
R1948  -  [0R0402-PAD]  146.59 70.61 180 top
R1949  -  [0R0402-PAD]  138.21 68.45 0 bottom
R1950  0R2J-2-GP  [R402H16]  129.83 45.34 0 top
R1951  -  [0R0402-PAD]  130.84 45.34 0 top
R1980  -  [0R0402-PAD]  143.16 8 180 bottom
R1984  -  [0R0402-PAD]  45.12 25.4 180 top
R1985  -  [0R0402-PAD]  45.25 23.62 270 bottom
R1993  1KR2J-1-GP  [R402H16]  136.56 51.69 90 bottom
R2006  1KR2J-1-GP  [R402H16]  106.46 132.84 90 bottom
R2007  1KR2J-1-GP  [R402H16]  106.46 134.11 90 bottom
R2012  1KR2J-1-GP  [R402H16]  87.89 138.71 90 top
R2021  10KR2J-3-GP  [R402H16]  106.84 141.99 180 bottom
R2032  10KR2J-3-GP  [R402H16]  100.11 142.37 270 top
R2040  49K9R2F-L-GP  [R402H16]  86.01 140.34 90 top
R2041  49K9R2F-L-GP  [R402H16]  86.01 139.32 90 top
R2081  180R3F-GP  [R603H22]  139.73 30.99 270 bottom
R2082  4K99R2F-L-GP  [R402H16]  131.48 37.9 180 bottom
R2083  2K2R2J-2-GP  [R402H16]  130.72 30.1 180 top
R2084  2K2R2J-2-GP  [R402H16]  131.73 30.1 180 top
R2085  4K7R2F-GP  [R402H16]  130.46 37.9 180 bottom
R2086  4K7R2F-GP  [R402H16]  131.22 33.02 0 bottom
R2087  4K7R2F-GP  [R402H16]  133.97 42.49 180 bottom
R2088  4K7R2F-GP  [R402H16]  131.94 42.49 180 bottom
R2089  4K7R2F-GP  [R402H16]  133.89 37.97 180 bottom
R2090  4K7R2F-GP  [R402H16]  132.49 37.95 180 bottom
R2091  10KR2J-3-GP  [R402H16]  145.96 32.51 270 top
R2106  0R0603-PAD-2-GP-U  [0R0603-PAD-1-U]  102.9 150.62 180 top
R2107  -  [0R0402-PAD]  83.85 137.29 0 top
R5201  10KR2J-3-GP  [R402H16]  105.19 14.61 0 top
R5202  10KR2J-3-GP  [R402H16]  106.21 14.61 0 top
R5203  10KR2J-3-GP  [R402H16]  107.22 14.61 0 top
R5204  10KR2J-3-GP  [R402H16]  105.06 24.38 0 top
R5205  10KR2J-3-GP  [R402H16]  108.24 14.61 0 top
R5206  10KR2J-3-GP  [R402H16]  106.08 24.38 0 top
R5207  10KR2J-3-GP  [R402H16]  108.11 24.38 0 top
R5208  10KR2J-3-GP  [R402H16]  107.09 24.38 0 top
R5209  10KR2J-3-GP  [R402H16]  126.14 19.05 270 top
R5210  47R2J-2-GP  [R402H16]  123.1 15.88 90 top
R5211  47R2J-2-GP  [R402H16]  121.57 20.19 0 bottom
R5212  100R2J-2-GP  [R402H14]  126.14 18.03 90 top
R5213  4K7R2J-2-GP  [R402H16]  123.1 14.86 90 top
R5214  4K7R2J-2-GP  [R402H16]  125.64 20.19 0 bottom
R5215  1KR2J-1-GP  [R402H16]  107.09 26.67 0 top
R5216  10KR2J-3-GP  [R402H16]  108.11 26.67 180 top
R5217  -  [0R0402-PAD]  122.97 28.45 270 top
R5218  1KR2J-1-GP  [R402H16]  118.14 23.62 270 top
R5219  100R2J-2-GP  [R402H14]  116.24 23.62 270 top
R6701  0R3J-0-U-GP  [R603H22]  82.58 64.41 90 top
R6702  10KR2J-3-GP  [R402H16]  85.76 61.72 180 top
R6703  100KR2J-1-GP  [R402H16]  86.77 61.72 180 top
R6704  100KR2J-1-GP  [R402H16]  82.2 63.25 90 top
R6705  100KR2J-1-GP  [R402H16]  104.43 61.59 270 top
R6706  0R2J-2-GP  [R402H16]  102.9 61.98 0 top
R8511  10KR2J-3-GP  [R402H16]  20.48 186.18 270 top
R8513  10KR2J-3-GP  [R402H16]  22 188.09 90 top
R8514  100KR2J-1-GP  [R402H16]  148.24 55.88 90 top
R8515  1KR2J-1-GP  [R402H16]  150.86 58.01 180 top
R8516  100KR2J-1-GP  [R402H16]  159.16 59.69 180 top
R9501  22R2J-2-GP  [R402H16]  76.87 54.99 0 top
R9502  22R2J-2-GP  [R402H16]  75.85 54.99 0 top
R9503  4K7R2J-2-GP  [R402H16]  62.01 54.61 180 bottom
R9504  22R2J-2-GP  [R402H16]  72.8 58.55 90 top
R9505  10KR2J-3-GP  [R402H16]  60.49 55.24 90 bottom
R9506  22R2J-2-GP  [R402H16]  72.8 59.56 90 top
R9507  10KR2J-3-GP  [R402H16]  76.11 66.17 90 top
R9508  10KR2J-3-GP  [R402H16]  78.01 66.17 90 top
R9509  -  [0R0402-PAD]  76.11 65.02 90 top
R9510  10KR2J-3-GP  [R402H16]  60.74 79.25 0 top
R9511  20KR2J-L2-GP  [R402H16]  63.03 80.64 270 top
R9519  6K2R2J-1-GP  [R402H16]  72.8 57.53 270 top
R9521  4K7R2J-2-GP  [R402H16]  56.68 54.61 180 bottom
R9525  4K7R2J-2-GP  [R402H16]  63.03 54.61 180 bottom
R9527  -  [0R0402-PAD]  63.91 51.18 180 top
R9528  4K7R2J-2-GP  [R402H16]  64.04 53.49 180 bottom
R9530  -  [0R0402-PAD]  64.93 51.18 180 top
R9531  6K2R2F-GP  [R402H16]  72.8 56.52 270 top
R9532  10KR2J-3-GP  [R402H16]  79.66 53.72 90 bottom
R9533  10KR2J-3-GP  [R402H16]  79.66 54.74 90 bottom
R9534  47R2J-2-GP  [R402H16]  79.66 54.74 270 top
R9535  47R2J-2-GP  [R402H16]  79.66 53.72 270 top
R9536  -  [0R0402-PAD]  65.95 51.18 180 top
R9540  4K7R2J-2-GP  [R402H16]  79.66 55.75 90 top
R9541  4K7R2J-2-GP  [R402H16]  79.66 55.75 270 bottom
R9542  10KR2J-3-GP  [R402H16]  79.66 52.7 90 top
R9543  10KR2J-3-GP  [R402H16]  85.55 51.05 0 top
R9544  10KR2J-3-GP  [R402H16]  76.11 67.18 90 top
R9545  10KR2J-3-GP  [R402H16]  58.58 73.79 180 bottom
R9546  -  [0R0402-PAD]  66.96 51.18 180 top
R9547  1MR2J-1-GP  [R402H16]  68.41 51.61 90 top
R9548  4K7R2J-2-GP  [R402H16]  65.08 53.49 180 bottom
R9553  0R0402-PAD-2-GP  [0R0402-PAD-1]  58.71 79.25 180 top
R9554  10KR2J-3-GP  [R402H16]  72.93 74.68 90 top
R9555  0R0402-PAD-2-GP  [0R0402-PAD-1]  59.72 79.25 180 top
R9556  -  [0R0402-PAD]  80.3 49.15 90 bottom
R9557  10KR2J-3-GP  [R402H16]  86.14 53.72 270 top
R9563  10KR2J-3-GP  [R402H16]  86.14 54.74 90 top
R9601  47KR2J-2-GP  [R402H16]  72.78 62.51 90 bottom
R9602  330KR2J-L1-GP  [R402H16]  72.78 63.53 90 bottom
R9603  100KR2J-1-GP  [R402H16]  72.78 64.54 270 bottom
R9604  47KR2J-2-GP  [R402H16]  64.8 65.79 270 bottom
R9605  1KR2J-1-GP  [R402H16]  64.42 67.31 0 bottom
R9609  47KR2J-2-GP  [R402H16]  57.69 66.42 0 bottom
R9901  -  [0R0805-PAD]  17.69 223.9 0 bottom
R9902  1KR2J-1-GP  [R402H16]  19.16 210.69 270 top
R9903  1KR2J-1-GP  [R402H16]  17.81 224.66 0 top
R9904  1KR2J-1-GP  [R402H16]  16.67 224.66 0 top
R9905  0R0603-PAD-2-GP-U  [0R0603-PAD-1-U]  22.64 224.54 180 bottom
R9906  150R2J-L1-GP-U  [R402H16]  43.21 224.16 0 top
R9907  1KR2J-1-GP  [R402H16]  44.36 224.16 0 top
R9908  0R2J-2-GP  [R402H16]  47.84 223.52 270 top
R9909  1K5R2J-3-GP  [R402H16]  47.84 224.54 270 top
R9910  -  [0R0402-PAD]  46.39 224.03 180 top
R9911  -  [0R0402-PAD]  52.36 220.34 90 top
R9912  -  [0R0402-PAD]  52.36 221.49 90 top
R9913  -  [0R0402-PAD]  28.99 224.16 180 top
R9914  -  [0R0402-PAD]  52.36 222.63 270 top
R9915  -  [0R0402-PAD]  50.58 224.16 0 top
R9916  -  [0R0402-PAD]  38.01 224.16 0 top
R9917  -  [0R0402-PAD]  39.02 224.16 0 top
R9918  51R2J-2-GP  [R402H16]  36.99 224.16 180 top
R9919  -  [0R0402-PAD]  35.97 224.16 180 top
R9920  -  [0R0402-PAD]  34.96 224.16 0 top
R9921  0R2J-2-GP  [R402H16]  52.36 223.65 90 top
R9922  0R2J-2-GP  [R402H16]  49.56 224.16 180 top
R9923  -  [0R0402-PAD]  30.01 224.16 180 top
R9924  0R0603-PAD-2-GP-U  [0R0603-PAD-1-U]  23.91 224.54 180 bottom
R9925  -  [0R0402-PAD]  33.94 224.16 0 top
R9926  -  [0R0402-PAD]  18.83 224.66 180 top
R9927  1KR2J-1-GP  [R402H16]  32.93 224.16 0 top
R9928  -  [0R0402-PAD]  42.07 224.16 0 top
R9929  100KR2J-1-GP  [R402H16]  41.05 224.16 0 top
R9930  1KR2J-1-GP  [R402H16]  29.62 224.41 180 bottom
R9931  0R2J-2-GP  [R402H16]  40.04 224.16 180 top
R9932  1K5R2J-3-GP  [R402H16]  26.45 224.41 0 bottom
R9933  -  [0R0402-PAD]  28.61 224.41 0 bottom
R9934  51R2J-2-GP  [R402H16]  15.53 224.66 0 top
R79171  1MR2J-1-GP  [R402H16]  78.14 49.66 180 top
R79172  1MR2J-1-GP  [R402H16]  77.12 51.56 180 top
R79174  4K7R2J-2-GP  [R402H16]  54.52 50.67 90 top
R79188  10KR2J-3-GP  [R402H16]  72.93 73.66 270 top
R79205  10KR2J-3-GP  [R402H16]  68.36 82.68 90 top
R79236  10KR2J-3-GP  [R402H16]  53.88 57.28 270 bottom
R79237  10KR2J-3-GP  [R402H16]  53.88 58.29 90 bottom
R79612  75R3F-GP  [R603H22]  65.29 12.27 270 top
R79618  -  [0R0402-PAD]  83.57 26.29 180 top
R79619  1R5J-2-GP  [R805H24]  37.88 39.12 270 bottom
R79621  10KR2F-2-GP  [R402H16]  42.2 24.64 90 top
R79622  D33R6F-GP  [R1206H26]  45.37 35.69 270 bottom
R79623  300KR2F-GP  [R402H16]  39.4 23.44 270 top
R79625  10KR2F-2-GP  [R402H16]  42.2 24.64 270 bottom
R79627  300KR2F-GP  [R402H16]  39.4 26.29 270 top
R79628  100KR2F-L1-GP  [R402H16]  35.59 21.34 180 bottom
R79630  200R5J-GP  [R805H24]  37.5 31.37 90 bottom
R79631  0R1206-PAD-1-GP  [0R1206-PAD-1]  45.37 37.97 270 top
R79633  -  [0R0402-PAD]  40.09 22 0 top
R79634  -  [0R0402-PAD]  39.07 22 0 top
R79647  0R2J-2-GP  [R402H16]  35.09 62.23 180 top
R79648  0R2J-2-GP  [R402H16]  35.09 60.33 0 top
R79656  100R2F-L1-GP-U  [R402H14]  45.75 101.98 180 top
R79657  0R2J-2-GP  [R402H16]  82.2 62.23 270 top
R79658  0R2J-2-GP  [R402H16]  84.74 61.65 0 top
R79668  100KR2J-1-GP  [R402H16]  83.73 61.72 0 top
R79687  10KR2J-3-GP  [R402H16]  42.45 86.87 180 bottom
R79689  10KR2J-3-GP  [R402H16]  42.45 93.09 0 bottom
R79690  1KR2F-3-GP  [R402H16]  45.75 103.89 180 top
R79691  10KR2J-3-GP  [R402H16]  43.21 119 180 top
R79697  0R2J-2-GP  [R402H16]  100.87 57.15 90 top
R79698  0R2J-2-GP  [R402H16]  100.87 55.88 90 top
R79699  0R2J-2-GP  [R402H16]  100.87 54.86 90 top
R79700  0R2J-2-GP  [R402H16]  100.87 52.58 90 top
R79701  0R2J-2-GP  [R402H16]  100.87 51.56 90 top
R79702  0R2J-2-GP  [R402H16]  99.98 49.02 90 top
R79703  0R2J-2-GP  [R402H16]  99.98 48.01 90 top
R79704  0R2J-2-GP  [R402H16]  95.41 50.04 0 top
